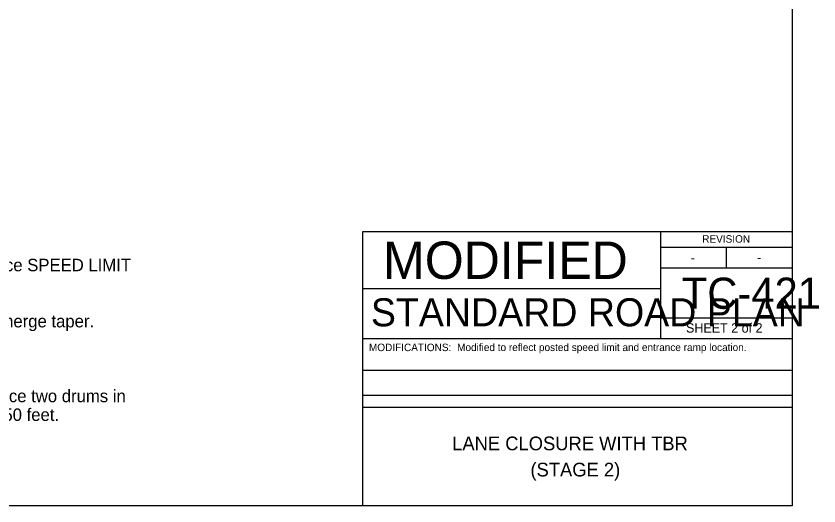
# Model space of a CAD drawing. Extents: x 10133 to 2270741, y 5363 to 1733450.
# Drawn here: x 30024 to 31311, y 7924 to 8710 of the extents above; entities that cross this region are included whole.
import ezdxf

# ---------------------------------------------------------------- set-up
doc = ezdxf.new("R2010")
doc.units = 0
for name, color, linetype in [('dsnStdDimension', 7, 'Continuous'), ('dsnStdLineWork', 7, 'Continuous'), ('dsnStdShading', 7, 'Continuous'), ('dsnStdTable', 7, 'Continuous'), ('SheetBorder', 7, 'Continuous')]:
    doc.layers.add(name, color=color, linetype=linetype)

msp = doc.modelspace()

# ---------------------------------------------------------------- linework, layer by layer
at = {"layer": 'dsnStdDimension'}
for p, q in [((31056.6, 8364), (31056.6, 8272.7)), ((31056.6, 8339.1), (31267.5, 8339.1)), ((31162.1, 8339.1), (31162.1, 8305.9)), ((31056.6, 8305.9), (31267.5, 8305.9)), ((30579.5, 8272.7), (31056.6, 8272.7)), ((31056.6, 8272.7), (31056.6, 8192.7)), ((31267.5, 8224.9), (31056.6, 8224.9)), ((30579.5, 8192.7), (31267.5, 8192.7)), ((30579.5, 8141.7), (31267.5, 8141.7)), ((30579.5, 8101.7), (31267.5, 8101.7)), ((30579.5, 8082.7), (31267.5, 8082.7))]:
    msp.add_line(p, q, dxfattribs=at)
msp.add_lwpolyline([(30579.5, 8364), (31267.5, 8364), (31267.5, 7924), (30579.5, 7924)], close=True, dxfattribs=at)
at = {"layer": 'dsnStdLineWork'}
msp.add_lwpolyline([(30579.5, 8364), (31267.5, 8364), (31267.5, 7924), (30579.5, 7924)], close=True, dxfattribs=at)
at = {"layer": 'SheetBorder'}
msp.add_lwpolyline([(28132.5, 9944), (31267.5, 9944), (31267.5, 7924), (28132.5, 7924)], close=True, dxfattribs=at)

# ---------------------------------------------------------------- texts
at = {"layer": 'dsnStdDimension'}
for s, height, p in [('REVISION', 12, (31123.6, 8346.2)), ('-', 15, (31105.1, 8314.7)), ('-', 15, (31211.6, 8315.1)), ('TC-421', 50, (31090.9, 8240.2)), ('STANDARD ROAD PLAN', 45.001, (30592.6, 8212.1)), ('SHEET 2 of 2', 15, (31097.6, 8202)), ('Modified to reflect posted speed limit and entrance ramp location.', 12, (30730.8, 8172.4)), ('LANE CLOSURE WITH TBR', 22, (30722.9, 8013.3)), ('(STAGE 2)', 22, (30848.3, 7971.3))]:
    msp.add_text(s, height=height, dxfattribs=at).set_placement(p)
at = {"layer": 'dsnStdShading'}
msp.add_text('MODIFICATIONS:', height=12, dxfattribs=at).set_placement((30589.5, 8172.3))
at = {"layer": 'dsnStdTable'}
for s, p in [('Place SPEED LIMIT AHEAD sign and SPEED LIMIT 55 sign prior to the lane closure as shown. Place SPEED LIMIT', (28828.9, 8300.4)), ('For traffic control zones lasting more than 4 hours, place a Speed Feedback Sign at the end of the merge taper.', (28828.9, 8210.4)), ('For lanes closed to traffic, place two drums every 1000 feet. For full depth excavations in a closed lane, place two drums in ', (28748.9, 8090.4)), ('front of each location. Additional drums need not be placed for full depth excavations spaced closer than 150 feet.', (28748.9, 8060.4))]:
    msp.add_text(s, height=20, dxfattribs=at).set_placement(p)
at = {"layer": 'SheetBorder'}
msp.add_text('MODIFIED', height=60, dxfattribs=at).set_placement((30612.1, 8288.1))

doc.saveas('drawing.dxf')
